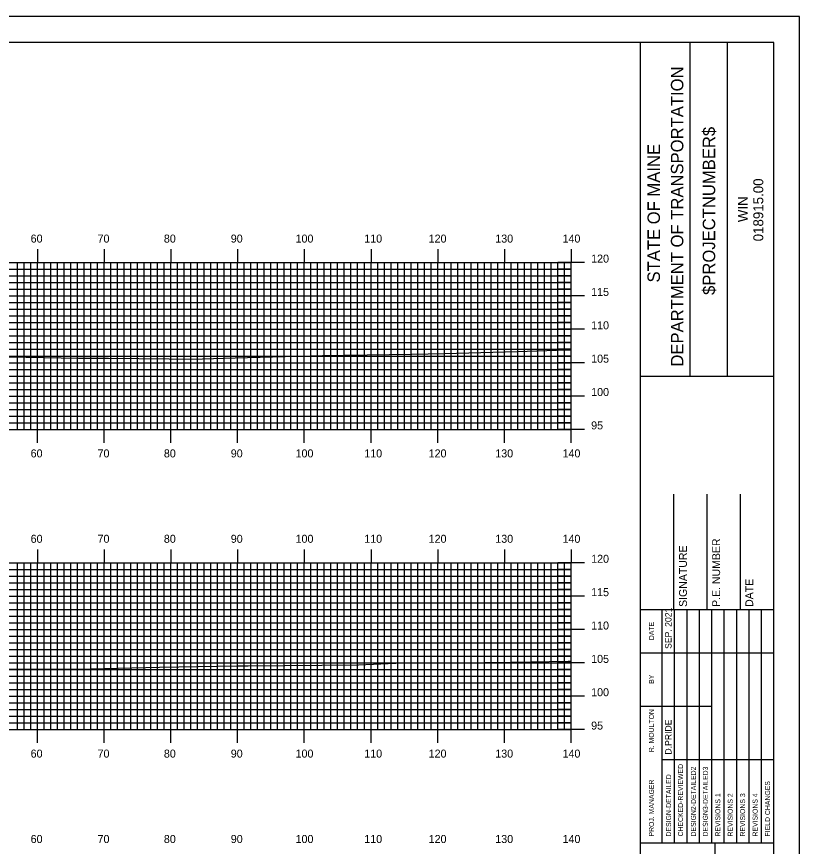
# Model space of a CAD drawing. Extents: x 1765726 to 1766069, y 442591 to 442811.
# Drawn here: x 1765948.8 to 1766066.1, y 442686.2 to 442810.5 of the extents above; entities that cross this region are included whole.
import ezdxf

# ---------------------------------------------------------------- set-up
doc = ezdxf.new("R2010")
doc.units = 0
for name, color, linetype in [('BORDER', 7, 'Continuous'), ('H_V ANNOTATION', 7, 'Continuous'), ('MAJOR', 7, 'Continuous'), ('MINOR', 7, 'Continuous'), ('PLOT BOUNDARY', 7, 'Continuous'), ('S_Roadway_Centerline', 7, 'Continuous')]:
    doc.layers.add(name, color=color, linetype=linetype)

msp = doc.modelspace()

# ---------------------------------------------------------------- linework, layer by layer
at = {"layer": 'BORDER'}
for p, q in [((1766042.28, 442596.67), (1766042.28, 442806.67)), ((1766049.74, 442756.66), (1766049.74, 442806.66)), ((1766055.33, 442756.66), (1766055.33, 442806.66)), ((1766042.29, 442756.65), (1766062.28, 442756.65)), ((1766047.28, 442721.67), (1766047.28, 442738.97)), ((1766052.28, 442721.67), (1766052.28, 442738.97)), ((1766057.28, 442721.67), (1766057.28, 442738.97)), ((1766042.28, 442721.67), (1766062.28, 442721.67)), ((1766042.28, 442686.67), (1766062.28, 442686.67)), ((1766053.47, 442616.67), (1766053.47, 442686.67))]:
    msp.add_line(p, q, dxfattribs=at)
msp.add_lwpolyline([(1765742.28, 442596.67), (1766062.28, 442596.67), (1766062.28, 442806.67), (1765742.28, 442806.67)], close=True, dxfattribs=at)
for points in [[(1766045.51, 442715.17), (1766045.51, 442721.67)], [(1766047.38, 442686.68), (1766047.38, 442721.67)], [(1766049.24, 442721.67), (1766049.24, 442686.68)], [(1766051.11, 442686.68), (1766051.11, 442721.67)], [(1766052.97, 442686.68), (1766052.97, 442721.67)], [(1766054.83, 442686.68), (1766054.83, 442721.67)], [(1766056.7, 442686.68), (1766056.7, 442721.67)], [(1766058.56, 442686.68), (1766058.56, 442721.67)], [(1766060.42, 442686.68), (1766060.42, 442721.67)], [(1766045.52, 442686.68), (1766045.52, 442720.26)], [(1766042.28, 442715.17), (1766062.28, 442715.17)], [(1766042.28, 442707.17), (1766045.52, 442707.17)], [(1766045.51, 442707.17), (1766052.97, 442707.17)], [(1766045.51, 442699.17), (1766062.28, 442699.17)]]:
    msp.add_lwpolyline(points, dxfattribs=at)
at = {"layer": 'MAJOR'}
for p, q in [((1765951.88, 442775.67), (1765951.88, 442773.67)), ((1765961.88, 442775.67), (1765961.88, 442773.67)), ((1765971.88, 442775.67), (1765971.88, 442773.67)), ((1765981.88, 442775.67), (1765981.88, 442773.67)), ((1765991.88, 442775.67), (1765991.88, 442773.67)), ((1766001.88, 442775.67), (1766001.88, 442773.67)), ((1766011.88, 442775.67), (1766011.88, 442773.67)), ((1766021.88, 442775.67), (1766021.88, 442773.67)), ((1766031.88, 442775.67), (1766031.88, 442773.67)), ((1765751.88, 442773.67), (1766031.88, 442773.67)), ((1765751.88, 442773.67), (1766031.88, 442773.67)), ((1765951.88, 442748.67), (1765951.88, 442773.67)), ((1765961.88, 442748.67), (1765961.88, 442773.67)), ((1765971.88, 442748.67), (1765971.88, 442773.67)), ((1765981.88, 442748.67), (1765981.88, 442773.67)), ((1765991.88, 442748.67), (1765991.88, 442773.67)), ((1766001.88, 442748.67), (1766001.88, 442773.67)), ((1766011.88, 442748.67), (1766011.88, 442773.67)), ((1766021.88, 442748.67), (1766021.88, 442773.67)), ((1766033.89, 442773.67), (1766029.88, 442773.67)), ((1766031.88, 442748.67), (1766031.88, 442773.67)), ((1766031.88, 442748.67), (1766031.88, 442773.67)), ((1765751.88, 442768.67), (1766031.88, 442768.67)), ((1766033.89, 442768.67), (1766029.88, 442768.67)), ((1765751.88, 442763.67), (1766031.88, 442763.67)), ((1766033.89, 442763.67), (1766029.88, 442763.67)), ((1765751.88, 442758.67), (1766031.88, 442758.67)), ((1766033.89, 442758.67), (1766029.88, 442758.67)), ((1765751.88, 442753.67), (1766031.88, 442753.67)), ((1766033.89, 442753.67), (1766029.88, 442753.67)), ((1765751.88, 442748.67), (1766031.88, 442748.67)), ((1765751.88, 442748.67), (1766031.88, 442748.67)), ((1765951.88, 442746.66), (1765951.88, 442748.67)), ((1765961.88, 442746.66), (1765961.88, 442748.67)), ((1765971.88, 442746.66), (1765971.88, 442748.67)), ((1765981.88, 442746.66), (1765981.88, 442748.67)), ((1765991.88, 442746.66), (1765991.88, 442748.67)), ((1766001.88, 442746.66), (1766001.88, 442748.67)), ((1766011.88, 442746.66), (1766011.88, 442748.67)), ((1766021.88, 442746.66), (1766021.88, 442748.67)), ((1766033.89, 442748.67), (1766029.88, 442748.67)), ((1766031.88, 442746.66), (1766031.88, 442748.67)), ((1765951.88, 442730.67), (1765951.88, 442728.67)), ((1765961.88, 442730.67), (1765961.88, 442728.67)), ((1765971.88, 442730.67), (1765971.88, 442728.67)), ((1765981.88, 442730.67), (1765981.88, 442728.67)), ((1765991.88, 442730.67), (1765991.88, 442728.67)), ((1766001.88, 442730.67), (1766001.88, 442728.67)), ((1766011.88, 442730.67), (1766011.88, 442728.67)), ((1766021.88, 442730.67), (1766021.88, 442728.67)), ((1766031.88, 442730.67), (1766031.88, 442728.67)), ((1765751.88, 442728.67), (1766031.88, 442728.67)), ((1765751.88, 442728.67), (1766031.88, 442728.67)), ((1765951.88, 442703.67), (1765951.88, 442728.67)), ((1765961.88, 442703.67), (1765961.88, 442728.67)), ((1765971.88, 442703.67), (1765971.88, 442728.67)), ((1765981.88, 442703.67), (1765981.88, 442728.67)), ((1765991.88, 442703.67), (1765991.88, 442728.67)), ((1766001.88, 442703.67), (1766001.88, 442728.67)), ((1766011.88, 442703.67), (1766011.88, 442728.67)), ((1766021.88, 442703.67), (1766021.88, 442728.67)), ((1766033.89, 442728.67), (1766029.88, 442728.67)), ((1766031.88, 442703.67), (1766031.88, 442728.67)), ((1766031.88, 442703.67), (1766031.88, 442728.67)), ((1765751.88, 442723.67), (1766031.88, 442723.67)), ((1766033.89, 442723.67), (1766029.88, 442723.67)), ((1765751.88, 442718.67), (1766031.88, 442718.67)), ((1766033.89, 442718.67), (1766029.88, 442718.67)), ((1765751.88, 442713.67), (1766031.88, 442713.67)), ((1766033.89, 442713.67), (1766029.88, 442713.67)), ((1765751.88, 442708.67), (1766031.88, 442708.67)), ((1766033.89, 442708.67), (1766029.88, 442708.67)), ((1765751.88, 442703.67), (1766031.88, 442703.67)), ((1765751.88, 442703.67), (1766031.88, 442703.67)), ((1765951.88, 442701.66), (1765951.88, 442703.67)), ((1765961.88, 442701.66), (1765961.88, 442703.67)), ((1765971.88, 442701.66), (1765971.88, 442703.67)), ((1765981.88, 442701.66), (1765981.88, 442703.67)), ((1765991.88, 442701.66), (1765991.88, 442703.67)), ((1766001.88, 442701.66), (1766001.88, 442703.67)), ((1766011.88, 442701.66), (1766011.88, 442703.67)), ((1766021.88, 442701.66), (1766021.88, 442703.67)), ((1766033.89, 442703.67), (1766029.88, 442703.67)), ((1766031.88, 442701.66), (1766031.88, 442703.67))]:
    msp.add_line(p, q, dxfattribs=at)
at = {"layer": 'MINOR'}
for p, q in [((1765948.88, 442748.67), (1765948.88, 442773.67)), ((1765949.88, 442748.67), (1765949.88, 442773.67)), ((1765950.88, 442748.67), (1765950.88, 442773.67)), ((1765952.88, 442748.67), (1765952.88, 442773.67)), ((1765953.88, 442748.67), (1765953.88, 442773.67)), ((1765954.88, 442748.67), (1765954.88, 442773.67)), ((1765955.88, 442748.67), (1765955.88, 442773.67)), ((1765956.88, 442748.67), (1765956.88, 442773.67)), ((1765957.88, 442748.67), (1765957.88, 442773.67)), ((1765958.88, 442748.67), (1765958.88, 442773.67)), ((1765959.88, 442748.67), (1765959.88, 442773.67)), ((1765960.88, 442748.67), (1765960.88, 442773.67)), ((1765962.88, 442748.67), (1765962.88, 442773.67)), ((1765963.88, 442748.67), (1765963.88, 442773.67)), ((1765964.88, 442748.67), (1765964.88, 442773.67)), ((1765965.88, 442748.67), (1765965.88, 442773.67)), ((1765966.88, 442748.67), (1765966.88, 442773.67)), ((1765967.88, 442748.67), (1765967.88, 442773.67)), ((1765968.88, 442748.67), (1765968.88, 442773.67)), ((1765969.88, 442748.67), (1765969.88, 442773.67)), ((1765970.88, 442748.67), (1765970.88, 442773.67)), ((1765972.88, 442748.67), (1765972.88, 442773.67)), ((1765973.88, 442748.67), (1765973.88, 442773.67)), ((1765974.88, 442748.67), (1765974.88, 442773.67)), ((1765975.88, 442748.67), (1765975.88, 442773.67)), ((1765976.88, 442748.67), (1765976.88, 442773.67)), ((1765977.88, 442748.67), (1765977.88, 442773.67)), ((1765978.88, 442748.67), (1765978.88, 442773.67)), ((1765979.88, 442748.67), (1765979.88, 442773.67)), ((1765980.88, 442748.67), (1765980.88, 442773.67)), ((1765982.88, 442748.67), (1765982.88, 442773.67)), ((1765983.88, 442748.67), (1765983.88, 442773.67)), ((1765984.88, 442748.67), (1765984.88, 442773.67)), ((1765985.88, 442748.67), (1765985.88, 442773.67)), ((1765986.88, 442748.67), (1765986.88, 442773.67)), ((1765987.88, 442748.67), (1765987.88, 442773.67)), ((1765988.88, 442748.67), (1765988.88, 442773.67)), ((1765989.88, 442748.67), (1765989.88, 442773.67)), ((1765990.88, 442748.67), (1765990.88, 442773.67)), ((1765992.88, 442748.67), (1765992.88, 442773.67)), ((1765993.88, 442748.67), (1765993.88, 442773.67)), ((1765994.88, 442748.67), (1765994.88, 442773.67)), ((1765995.88, 442748.67), (1765995.88, 442773.67)), ((1765996.88, 442748.67), (1765996.88, 442773.67)), ((1765997.88, 442748.67), (1765997.88, 442773.67)), ((1765998.88, 442748.67), (1765998.88, 442773.67)), ((1765999.88, 442748.67), (1765999.88, 442773.67)), ((1766000.88, 442748.67), (1766000.88, 442773.67)), ((1766002.88, 442748.67), (1766002.88, 442773.67)), ((1766003.88, 442748.67), (1766003.88, 442773.67)), ((1766004.88, 442748.67), (1766004.88, 442773.67)), ((1766005.88, 442748.67), (1766005.88, 442773.67)), ((1766006.88, 442748.67), (1766006.88, 442773.67)), ((1766007.88, 442748.67), (1766007.88, 442773.67)), ((1766008.88, 442748.67), (1766008.88, 442773.67)), ((1766009.88, 442748.67), (1766009.88, 442773.67)), ((1766010.88, 442748.67), (1766010.88, 442773.67)), ((1766012.88, 442748.67), (1766012.88, 442773.67)), ((1766013.88, 442748.67), (1766013.88, 442773.67)), ((1766014.88, 442748.67), (1766014.88, 442773.67)), ((1766015.88, 442748.67), (1766015.88, 442773.67)), ((1766016.88, 442748.67), (1766016.88, 442773.67)), ((1766017.88, 442748.67), (1766017.88, 442773.67)), ((1766018.88, 442748.67), (1766018.88, 442773.67)), ((1766019.88, 442748.67), (1766019.88, 442773.67)), ((1766020.88, 442748.67), (1766020.88, 442773.67)), ((1766022.88, 442748.67), (1766022.88, 442773.67)), ((1766023.88, 442748.67), (1766023.88, 442773.67)), ((1766024.88, 442748.67), (1766024.88, 442773.67)), ((1766025.88, 442748.67), (1766025.88, 442773.67)), ((1766026.88, 442748.67), (1766026.88, 442773.67)), ((1766027.88, 442748.67), (1766027.88, 442773.67)), ((1766028.88, 442748.67), (1766028.88, 442773.67)), ((1766029.88, 442748.67), (1766029.88, 442773.67)), ((1766030.88, 442748.67), (1766030.88, 442773.67)), ((1765751.88, 442772.67), (1766031.88, 442772.67)), ((1766031.88, 442772.67), (1766029.88, 442772.67)), ((1765751.88, 442771.67), (1766031.88, 442771.67)), ((1766031.88, 442771.67), (1766029.88, 442771.67)), ((1765751.88, 442770.67), (1766031.88, 442770.67)), ((1766031.88, 442770.67), (1766029.88, 442770.67)), ((1765751.88, 442769.67), (1766031.88, 442769.67)), ((1766031.88, 442769.67), (1766029.88, 442769.67)), ((1765751.88, 442767.67), (1766031.88, 442767.67)), ((1766031.88, 442767.67), (1766029.88, 442767.67)), ((1765751.88, 442766.67), (1766031.88, 442766.67)), ((1766031.88, 442766.67), (1766029.88, 442766.67)), ((1765751.88, 442765.67), (1766031.88, 442765.67)), ((1766031.88, 442765.67), (1766029.88, 442765.67)), ((1765751.88, 442764.67), (1766031.88, 442764.67)), ((1766031.88, 442764.67), (1766029.88, 442764.67)), ((1765751.88, 442762.67), (1766031.88, 442762.67)), ((1766031.88, 442762.67), (1766029.88, 442762.67)), ((1765751.88, 442761.67), (1766031.88, 442761.67)), ((1766031.88, 442761.67), (1766029.88, 442761.67)), ((1765751.88, 442760.67), (1766031.88, 442760.67)), ((1766031.88, 442760.67), (1766029.88, 442760.67)), ((1765751.88, 442759.67), (1766031.88, 442759.67)), ((1766031.88, 442759.67), (1766029.88, 442759.67)), ((1765751.88, 442757.67), (1766031.88, 442757.67)), ((1766031.88, 442757.67), (1766029.88, 442757.67)), ((1765751.88, 442756.67), (1766031.88, 442756.67)), ((1766031.88, 442756.67), (1766029.88, 442756.67)), ((1765751.88, 442755.67), (1766031.88, 442755.67)), ((1766031.88, 442755.67), (1766029.88, 442755.67)), ((1765751.88, 442754.67), (1766031.88, 442754.67)), ((1766031.88, 442754.67), (1766029.88, 442754.67)), ((1765751.88, 442752.67), (1766031.88, 442752.67)), ((1766031.88, 442752.67), (1766029.88, 442752.67)), ((1765751.88, 442751.67), (1766031.88, 442751.67)), ((1766031.88, 442751.67), (1766029.88, 442751.67)), ((1765751.88, 442750.67), (1766031.88, 442750.67)), ((1766031.88, 442750.67), (1766029.88, 442750.67)), ((1765751.88, 442749.67), (1766031.88, 442749.67)), ((1766031.88, 442749.67), (1766029.88, 442749.67)), ((1765751.88, 442727.67), (1766031.88, 442727.67)), ((1765948.88, 442703.67), (1765948.88, 442728.67)), ((1765949.88, 442703.67), (1765949.88, 442728.67)), ((1765950.88, 442703.67), (1765950.88, 442728.67)), ((1765952.88, 442703.67), (1765952.88, 442728.67)), ((1765953.88, 442703.67), (1765953.88, 442728.67)), ((1765954.88, 442703.67), (1765954.88, 442728.67)), ((1765955.88, 442703.67), (1765955.88, 442728.67)), ((1765956.88, 442703.67), (1765956.88, 442728.67)), ((1765957.88, 442703.67), (1765957.88, 442728.67)), ((1765958.88, 442703.67), (1765958.88, 442728.67)), ((1765959.88, 442703.67), (1765959.88, 442728.67)), ((1765960.88, 442703.67), (1765960.88, 442728.67)), ((1765962.88, 442703.67), (1765962.88, 442728.67)), ((1765963.88, 442703.67), (1765963.88, 442728.67)), ((1765964.88, 442703.67), (1765964.88, 442728.67)), ((1765965.88, 442703.67), (1765965.88, 442728.67)), ((1765966.88, 442703.67), (1765966.88, 442728.67)), ((1765967.88, 442703.67), (1765967.88, 442728.67)), ((1765968.88, 442703.67), (1765968.88, 442728.67)), ((1765969.88, 442703.67), (1765969.88, 442728.67)), ((1765970.88, 442703.67), (1765970.88, 442728.67)), ((1765972.88, 442703.67), (1765972.88, 442728.67)), ((1765973.88, 442703.67), (1765973.88, 442728.67)), ((1765974.88, 442703.67), (1765974.88, 442728.67)), ((1765975.88, 442703.67), (1765975.88, 442728.67)), ((1765976.88, 442703.67), (1765976.88, 442728.67)), ((1765977.88, 442703.67), (1765977.88, 442728.67)), ((1765978.88, 442703.67), (1765978.88, 442728.67)), ((1765979.88, 442703.67), (1765979.88, 442728.67)), ((1765980.88, 442703.67), (1765980.88, 442728.67)), ((1765982.88, 442703.67), (1765982.88, 442728.67)), ((1765983.88, 442703.67), (1765983.88, 442728.67)), ((1765984.88, 442703.67), (1765984.88, 442728.67)), ((1765985.88, 442703.67), (1765985.88, 442728.67)), ((1765986.88, 442703.67), (1765986.88, 442728.67)), ((1765987.88, 442703.67), (1765987.88, 442728.67)), ((1765988.88, 442703.67), (1765988.88, 442728.67)), ((1765989.88, 442703.67), (1765989.88, 442728.67)), ((1765990.88, 442703.67), (1765990.88, 442728.67)), ((1765992.88, 442703.67), (1765992.88, 442728.67)), ((1765993.88, 442703.67), (1765993.88, 442728.67)), ((1765994.88, 442703.67), (1765994.88, 442728.67)), ((1765995.88, 442703.67), (1765995.88, 442728.67)), ((1765996.88, 442703.67), (1765996.88, 442728.67)), ((1765997.88, 442703.67), (1765997.88, 442728.67)), ((1765998.88, 442703.67), (1765998.88, 442728.67)), ((1765999.88, 442703.67), (1765999.88, 442728.67)), ((1766000.88, 442703.67), (1766000.88, 442728.67)), ((1766002.88, 442703.67), (1766002.88, 442728.67)), ((1766003.88, 442703.67), (1766003.88, 442728.67)), ((1766004.88, 442703.67), (1766004.88, 442728.67)), ((1766005.88, 442703.67), (1766005.88, 442728.67)), ((1766006.88, 442703.67), (1766006.88, 442728.67)), ((1766007.88, 442703.67), (1766007.88, 442728.67)), ((1766008.88, 442703.67), (1766008.88, 442728.67)), ((1766009.88, 442703.67), (1766009.88, 442728.67)), ((1766010.88, 442703.67), (1766010.88, 442728.67)), ((1766012.88, 442703.67), (1766012.88, 442728.67)), ((1766013.88, 442703.67), (1766013.88, 442728.67)), ((1766014.88, 442703.67), (1766014.88, 442728.67)), ((1766015.88, 442703.67), (1766015.88, 442728.67)), ((1766016.88, 442703.67), (1766016.88, 442728.67)), ((1766017.88, 442703.67), (1766017.88, 442728.67)), ((1766018.88, 442703.67), (1766018.88, 442728.67)), ((1766019.88, 442703.67), (1766019.88, 442728.67)), ((1766020.88, 442703.67), (1766020.88, 442728.67)), ((1766022.88, 442703.67), (1766022.88, 442728.67)), ((1766023.88, 442703.67), (1766023.88, 442728.67)), ((1766024.88, 442703.67), (1766024.88, 442728.67)), ((1766025.88, 442703.67), (1766025.88, 442728.67)), ((1766026.88, 442703.67), (1766026.88, 442728.67)), ((1766027.88, 442703.67), (1766027.88, 442728.67)), ((1766028.88, 442703.67), (1766028.88, 442728.67)), ((1766029.88, 442703.67), (1766029.88, 442728.67)), ((1766031.88, 442727.67), (1766029.88, 442727.67)), ((1766030.88, 442703.67), (1766030.88, 442728.67)), ((1765751.88, 442726.67), (1766031.88, 442726.67)), ((1766031.88, 442726.67), (1766029.88, 442726.67)), ((1765751.88, 442725.67), (1766031.88, 442725.67)), ((1766031.88, 442725.67), (1766029.88, 442725.67)), ((1765751.88, 442724.67), (1766031.88, 442724.67)), ((1766031.88, 442724.67), (1766029.88, 442724.67)), ((1765751.88, 442722.67), (1766031.88, 442722.67)), ((1766031.88, 442722.67), (1766029.88, 442722.67)), ((1765751.88, 442721.67), (1766031.88, 442721.67)), ((1766031.88, 442721.67), (1766029.88, 442721.67)), ((1765751.88, 442720.67), (1766031.88, 442720.67)), ((1766031.88, 442720.67), (1766029.88, 442720.67)), ((1765751.88, 442719.67), (1766031.88, 442719.67)), ((1766031.88, 442719.67), (1766029.88, 442719.67)), ((1765751.88, 442717.67), (1766031.88, 442717.67)), ((1766031.88, 442717.67), (1766029.88, 442717.67)), ((1765751.88, 442716.67), (1766031.88, 442716.67)), ((1766031.88, 442716.67), (1766029.88, 442716.67)), ((1765751.88, 442715.67), (1766031.88, 442715.67)), ((1766031.88, 442715.67), (1766029.88, 442715.67)), ((1765751.88, 442714.67), (1766031.88, 442714.67)), ((1766031.88, 442714.67), (1766029.88, 442714.67)), ((1765751.88, 442712.67), (1766031.88, 442712.67)), ((1766031.88, 442712.67), (1766029.88, 442712.67)), ((1765751.88, 442711.67), (1766031.88, 442711.67)), ((1766031.88, 442711.67), (1766029.88, 442711.67)), ((1765751.88, 442710.67), (1766031.88, 442710.67)), ((1766031.88, 442710.67), (1766029.88, 442710.67)), ((1765751.88, 442709.67), (1766031.88, 442709.67)), ((1766031.88, 442709.67), (1766029.88, 442709.67)), ((1765751.88, 442707.67), (1766031.88, 442707.67)), ((1765751.88, 442706.67), (1766031.88, 442706.67)), ((1766031.88, 442707.67), (1766029.88, 442707.67)), ((1766031.88, 442706.67), (1766029.88, 442706.67)), ((1765751.88, 442705.67), (1766031.88, 442705.67)), ((1766031.88, 442705.67), (1766029.88, 442705.67)), ((1765751.88, 442704.67), (1766031.88, 442704.67)), ((1766031.88, 442704.67), (1766029.88, 442704.67))]:
    msp.add_line(p, q, dxfattribs=at)
at = {"layer": 'PLOT BOUNDARY'}
msp.add_lwpolyline([(1765726.1, 442590.55), (1766066.1, 442590.55), (1766066.1, 442810.55), (1765726.1, 442810.55)], close=True, dxfattribs=at)
at = {"layer": 'S_Roadway_Centerline'}
for points in [[(1765944.96, 442759.62), (1765958.02, 442759.36), (1765962.53, 442759.35), (1765971.61, 442759.24), (1765974.93, 442759.22), (1765976.6, 442759.25), (1765981.54, 442759.39), (1765994.62, 442759.76), (1766008.02, 442759.97), (1766012.88, 442760.04), (1766023.79, 442760.36), (1766031.2, 442760.6), (1766031.88, 442760.61)], [(1765945.57, 442712.8), (1765957.67, 442712.72), (1765963.99, 442712.86), (1765970.15, 442713.05), (1765981.79, 442713.24), (1765983.47, 442713.24), (1765999.98, 442713.38), (1766006.7, 442713.68), (1766018.78, 442713.74), (1766019.22, 442713.73), (1766020.15, 442713.75), (1766031.41, 442713.91), (1766031.88, 442713.91)]]:
    msp.add_lwpolyline(points, dxfattribs=at)

# ---------------------------------------------------------------- texts
at = {"layer": 'BORDER'}
for s, height, p in [('DEPARTMENT OF TRANSPORTATION', 1.8635, (1766048.7, 442758.08)), ('$PROJECTNUMBER$', 1.8635, (1766053.47, 442768.82)), ('STATE OF MAINE', 1.8635, (1766045.19, 442770.69)), ('018915.00', 1.491, (1766060.68, 442776.86)), ('WIN', 1.491, (1766058.36, 442779.73)), ('P.E. NUMBER', 1.1811, (1766054.21, 442722.06)), ('SIGNATURE', 1.181, (1766049.24, 442722.06)), ('DATE', 1.181, (1766059.17, 442722.06)), ('SEP. 2021', 0.969, (1766046.93, 442715.76)), ('DATE', 0.743, (1766044.29, 442717.08)), ('BY', 0.743, (1766044.29, 442710.54)), ('R. MOULTON', 0.745, (1766044.29, 442700.28)), ('D.PRIDE', 0.969, (1766046.93, 442699.92)), ('CHECKED-REVIEWED', 0.7455, (1766048.65, 442687.65)), ('DESIGN2-DETAILED2', 0.7455, (1766050.58, 442687.65)), ('DESIGN3-DETAILED3', 0.7455, (1766052.37, 442687.65)), ('DESIGN-DETAILED', 0.7455, (1766046.86, 442687.65)), ('PROJ. MANAGER', 0.7455, (1766044.29, 442687.65)), ('FIELD CHANGES', 0.7455, (1766061.69, 442687.65)), ('REVISIONS 1', 0.7455, (1766054.24, 442687.65)), ('REVISIONS 2', 0.7455, (1766056.1, 442687.65)), ('REVISIONS 3', 0.7455, (1766057.96, 442687.65)), ('REVISIONS 4', 0.7455, (1766059.83, 442687.65))]:
    msp.add_text(s, height=height, rotation=90, dxfattribs=at).set_placement(p)
at = {"layer": 'H_V ANNOTATION'}
for s, p in [('60', (1765950.86, 442776.67)), ('70', (1765960.89, 442776.67)), ('80', (1765970.83, 442776.67)), ('90', (1765980.86, 442776.67)), ('100', (1765990.57, 442776.67)), ('110', (1766000.87, 442776.67)), ('120', (1766010.52, 442776.67)), ('130', (1766020.51, 442776.67)), ('140', (1766030.59, 442776.67)), ('120', (1766034.88, 442773.67)), ('115', (1766034.88, 442768.67)), ('110', (1766034.88, 442763.67)), ('105', (1766034.88, 442758.67)), ('100', (1766034.88, 442753.67)), ('95', (1766034.88, 442748.67)), ('60', (1765950.86, 442744.47)), ('70', (1765960.89, 442744.47)), ('80', (1765970.83, 442744.47)), ('90', (1765980.86, 442744.47)), ('100', (1765990.57, 442744.47)), ('110', (1766000.87, 442744.47)), ('120', (1766010.52, 442744.47)), ('130', (1766020.51, 442744.47)), ('140', (1766030.59, 442744.47)), ('60', (1765950.86, 442731.67)), ('70', (1765960.89, 442731.67)), ('80', (1765970.83, 442731.67)), ('90', (1765980.86, 442731.67)), ('100', (1765990.57, 442731.67)), ('110', (1766000.87, 442731.67)), ('120', (1766010.52, 442731.67)), ('130', (1766020.51, 442731.67)), ('140', (1766030.59, 442731.67)), ('120', (1766034.88, 442728.67)), ('115', (1766034.88, 442723.67)), ('110', (1766034.88, 442718.67)), ('105', (1766034.88, 442713.67)), ('100', (1766034.88, 442708.67)), ('95', (1766034.88, 442703.67)), ('60', (1765950.86, 442699.47)), ('70', (1765960.89, 442699.47)), ('80', (1765970.83, 442699.47)), ('90', (1765980.86, 442699.47)), ('100', (1765990.57, 442699.47)), ('110', (1766000.87, 442699.47)), ('120', (1766010.52, 442699.47)), ('130', (1766020.51, 442699.47)), ('140', (1766030.59, 442699.47)), ('60', (1765950.86, 442686.67)), ('70', (1765960.89, 442686.67)), ('80', (1765970.83, 442686.67)), ('90', (1765980.86, 442686.67)), ('100', (1765990.57, 442686.67)), ('110', (1766000.87, 442686.67)), ('120', (1766010.52, 442686.67)), ('130', (1766020.51, 442686.67)), ('140', (1766030.59, 442686.67))]:
    msp.add_text(s, height=1.2, dxfattribs=at).set_placement(p)

doc.saveas('drawing.dxf')
